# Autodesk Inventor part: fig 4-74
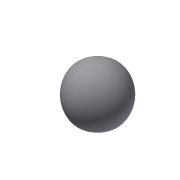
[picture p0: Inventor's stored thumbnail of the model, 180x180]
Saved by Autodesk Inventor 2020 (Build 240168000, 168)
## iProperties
Created: 2012-07
Part Number: fig 4-74
Material: Generic
Document SubType Name: Modeling
Designer: CADCIM
Density: 1 g/cm^3
Appearance: Default
Author: CADCIM
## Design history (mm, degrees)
feature "Form2"
body "Solid1"
body "Solid3"
